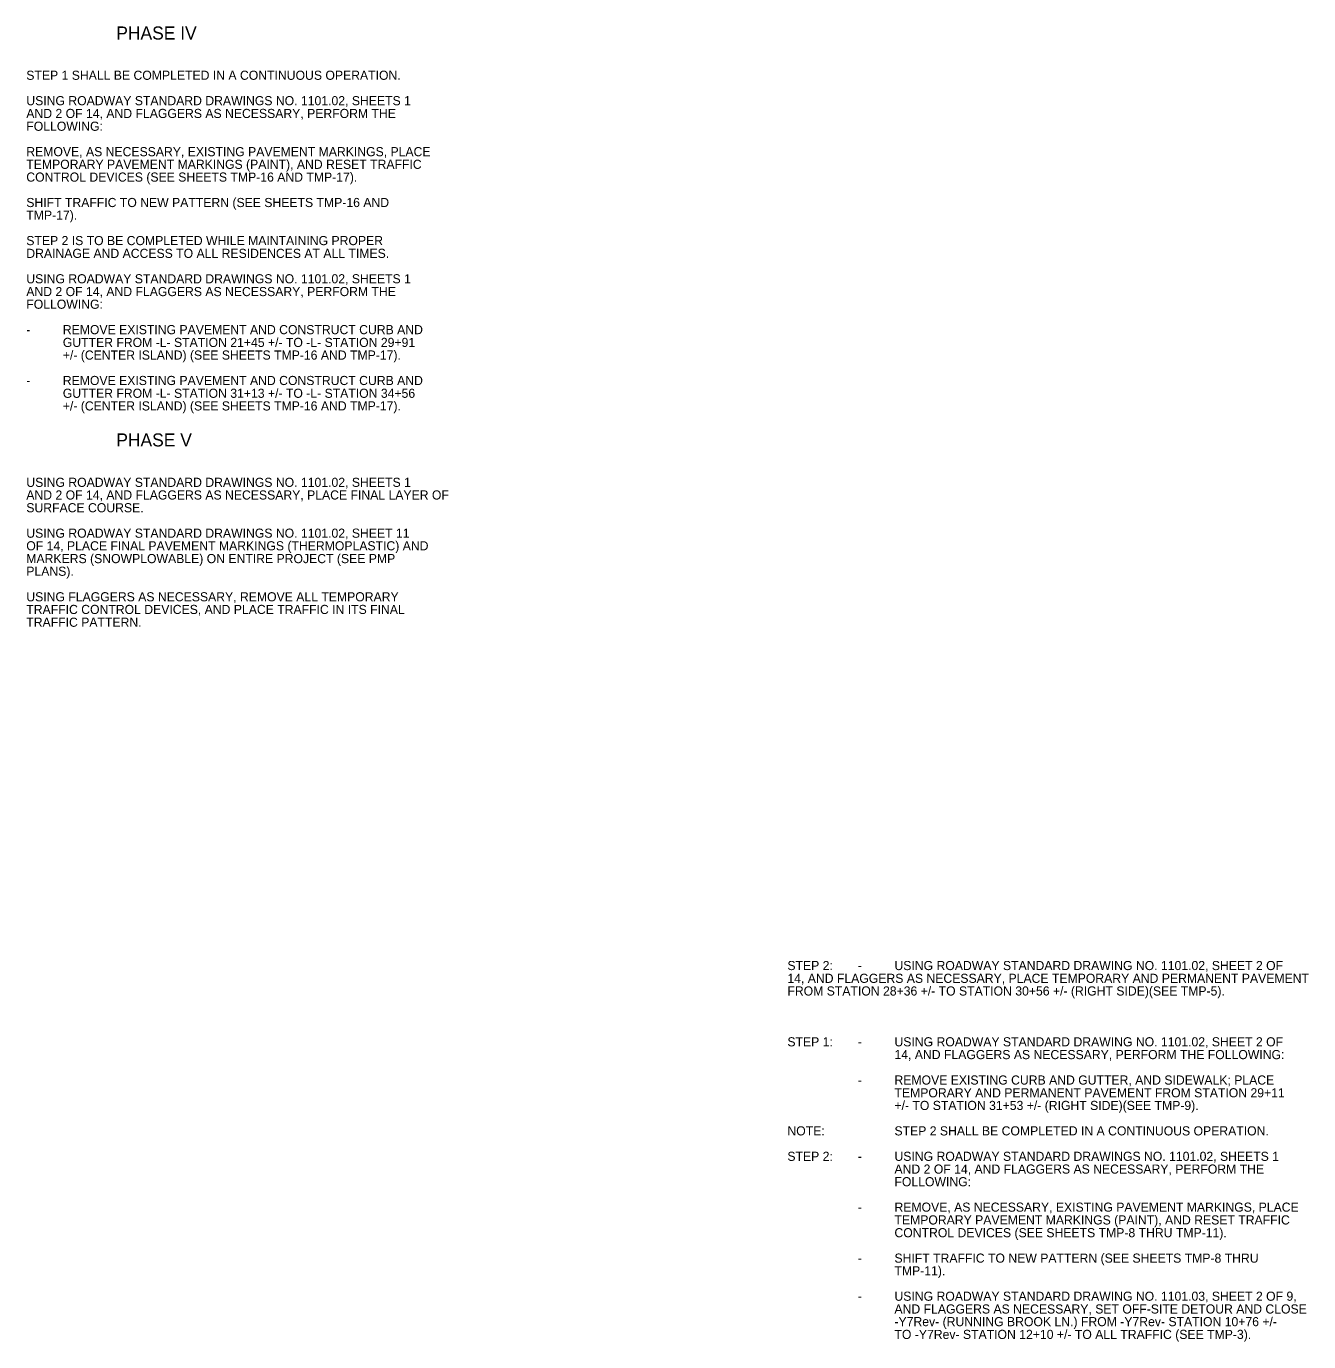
# Model space of a CAD drawing. Extents: x 764226 to 769781, y 650021 to 652521.
# Drawn here: x 765194 to 766178, y 651422 to 652431 of the extents above; entities that cross this region are included whole.
import ezdxf

# ---------------------------------------------------------------- set-up
doc = ezdxf.new("R2010")
doc.units = 0
doc.layers.add('Default', color=7, linetype='Continuous')

msp = doc.modelspace()

# ---------------------------------------------------------------- texts
at = {"layer": 'Default'}
for s, height, p in [('PHASE IV', 10, (765263.4, 652420.4)), ('STEP 1 SHALL BE COMPLETED IN A CONTINUOUS OPERATION.', 7, (765194.4, 652389.5)), ('USING ROADWAY STANDARD DRAWINGS NO. 1101.02, SHEETS 1 ', 7, (765194.4, 652370)), ('AND 2 OF 14, AND FLAGGERS AS NECESSARY, PERFORM THE ', 7, (765194.4, 652360.2)), ('FOLLOWING:', 7, (765194.4, 652350.4)), ('REMOVE, AS NECESSARY, EXISTING PAVEMENT MARKINGS, PLACE ', 7, (765194.4, 652330.9)), ('TEMPORARY PAVEMENT MARKINGS (PAINT), AND RESET TRAFFIC ', 7, (765194.4, 652321.2)), ('CONTROL DEVICES (SEE SHEETS TMP-16 AND TMP-17).', 7, (765194.4, 652311.4)), ('SHIFT TRAFFIC TO NEW PATTERN (SEE SHEETS TMP-16 AND ', 7, (765194.4, 652291.9)), ('TMP-17).', 7, (765194.4, 652282.2)), ('STEP 2 IS TO BE COMPLETED WHILE MAINTAINING PROPER ', 7, (765194.4, 652262.7)), ('DRAINAGE AND ACCESS TO ALL RESIDENCES AT ALL TIMES.', 7, (765194.4, 652252.9)), ('USING ROADWAY STANDARD DRAWINGS NO. 1101.02, SHEETS 1 ', 7, (765194.4, 652233.4)), ('AND 2 OF 14, AND FLAGGERS AS NECESSARY, PERFORM THE ', 7, (765194.4, 652223.6)), ('FOLLOWING:', 7, (765194.4, 652213.9)), ('-', 7, (765194.4, 652194.4)), ('REMOVE EXISTING PAVEMENT AND CONSTRUCT CURB AND ', 7, (765222.4, 652194.4)), ('GUTTER FROM -L- STATION 21+45 +/- TO -L- STATION 29+91 ', 7, (765222.4, 652184.6)), ('+/- (CENTER ISLAND) (SEE SHEETS TMP-16 AND TMP-17).', 7, (765222.4, 652174.9)), ('-', 7, (765194.4, 652155.4)), ('REMOVE EXISTING PAVEMENT AND CONSTRUCT CURB AND ', 7, (765222.4, 652155.4)), ('GUTTER FROM -L- STATION 31+13 +/- TO -L- STATION 34+56 ', 7, (765222.4, 652145.6)), ('+/- (CENTER ISLAND) (SEE SHEETS TMP-16 AND TMP-17).', 7, (765222.4, 652135.9)), ('PHASE V', 10, (765263.4, 652108.3)), ('USING ROADWAY STANDARD DRAWINGS NO. 1101.02, SHEETS 1 ', 7, (765194.4, 652077.3)), ('AND 2 OF 14, AND FLAGGERS AS NECESSARY, PLACE FINAL LAYER OF ', 7, (765194.4, 652067.6)), ('SURFACE COURSE.', 7, (765194.4, 652057.8)), ('USING ROADWAY STANDARD DRAWINGS NO. 1101.02, SHEET 11 ', 7, (765194.4, 652038.3)), ('OF 14, PLACE FINAL PAVEMENT MARKINGS (THERMOPLASTIC) AND ', 7, (765194.4, 652028.6)), ('MARKERS (SNOWPLOWABLE) ON ENTIRE PROJECT (SEE PMP ', 7, (765194.4, 652018.8)), ('PLANS).', 7, (765194.4, 652009.1)), ('USING FLAGGERS AS NECESSARY, REMOVE ALL TEMPORARY ', 7, (765194.4, 651989.5)), ('TRAFFIC CONTROL DEVICES, AND PLACE TRAFFIC IN ITS FINAL ', 7, (765194.4, 651979.8)), ('TRAFFIC PATTERN.', 7, (765194.4, 651970)), ('STEP 2:', 7, (765778.1, 651706.7)), ('USING ROADWAY STANDARD DRAWING NO. 1101.02, SHEET 2 OF ', 7, (765860.2, 651706.7)), ('14, AND FLAGGERS AS NECESSARY, PLACE TEMPORARY AND PERMANENT PAVEMENT ', 7, (765778.1, 651696.9)), ('-', 7, (765832.2, 651706.7)), ('FROM STATION 28+36 +/- TO STATION 30+56 +/- (RIGHT SIDE)(SEE TMP-5).', 7, (765778.1, 651687.2)), ('STEP 1:', 7, (765778.1, 651648.2)), ('-', 7, (765832.2, 651648.2)), ('USING ROADWAY STANDARD DRAWING NO. 1101.02, SHEET 2 OF ', 7, (765860.2, 651648.2)), ('14, AND FLAGGERS AS NECESSARY, PERFORM THE FOLLOWING:', 7, (765860.2, 651638.4)), ('-', 7, (765832.2, 651618.9)), ('REMOVE EXISTING CURB AND GUTTER, AND SIDEWALK; PLACE ', 7, (765860.2, 651618.9)), ('TEMPORARY AND PERMANENT PAVEMENT FROM STATION 29+11 ', 7, (765860.2, 651609.1)), ('+/- TO STATION 31+53 +/- (RIGHT SIDE)(SEE TMP-9).', 7, (765860.2, 651599.4)), ('NOTE: ', 7, (765778.1, 651579.9)), ('STEP 2 SHALL BE COMPLETED IN A CONTINUOUS OPERATION.', 7, (765860.2, 651579.9)), ('STEP 2:', 7, (765778.1, 651560.4)), ('-', 7, (765832.2, 651560.4)), ('USING ROADWAY STANDARD DRAWINGS NO. 1101.02, SHEETS 1 ', 7, (765860.2, 651560.4)), ('AND 2 OF 14, AND FLAGGERS AS NECESSARY, PERFORM THE ', 7, (765860.2, 651550.6)), ('FOLLOWING:', 7, (765860.2, 651540.9)), ('-', 7, (765832.2, 651521.4)), ('REMOVE, AS NECESSARY, EXISTING PAVEMENT MARKINGS, PLACE ', 7, (765860.2, 651521.4)), ('TEMPORARY PAVEMENT MARKINGS (PAINT), AND RESET TRAFFIC ', 7, (765860.2, 651511.6)), ('CONTROL DEVICES (SEE SHEETS TMP-8 THRU TMP-11).', 7, (765860.2, 651501.8)), ('SHIFT TRAFFIC TO NEW PATTERN (SEE SHEETS TMP-8 THRU ', 7, (765860.2, 651482.3)), ('-', 7, (765832.2, 651482.3)), ('TMP-11).', 7, (765860.2, 651472.6)), ('USING ROADWAY STANDARD DRAWING NO. 1101.03, SHEET 2 OF 9, ', 7, (765860.2, 651453.1)), ('-', 7, (765832.2, 651453.1)), ('AND FLAGGERS AS NECESSARY, SET OFF-SITE DETOUR AND CLOSE ', 7, (765860.2, 651443.3)), ('-Y7Rev- (RUNNING BROOK LN.) FROM -Y7Rev- STATION 10+76 +/- ', 7, (765860.2, 651433.6)), ('TO -Y7Rev- STATION 12+10 +/- TO ALL TRAFFIC (SEE TMP-3).', 7, (765860.2, 651423.8))]:
    msp.add_text(s, height=height, rotation=359.9999, dxfattribs=at).set_placement(p)

doc.saveas('drawing.dxf')
